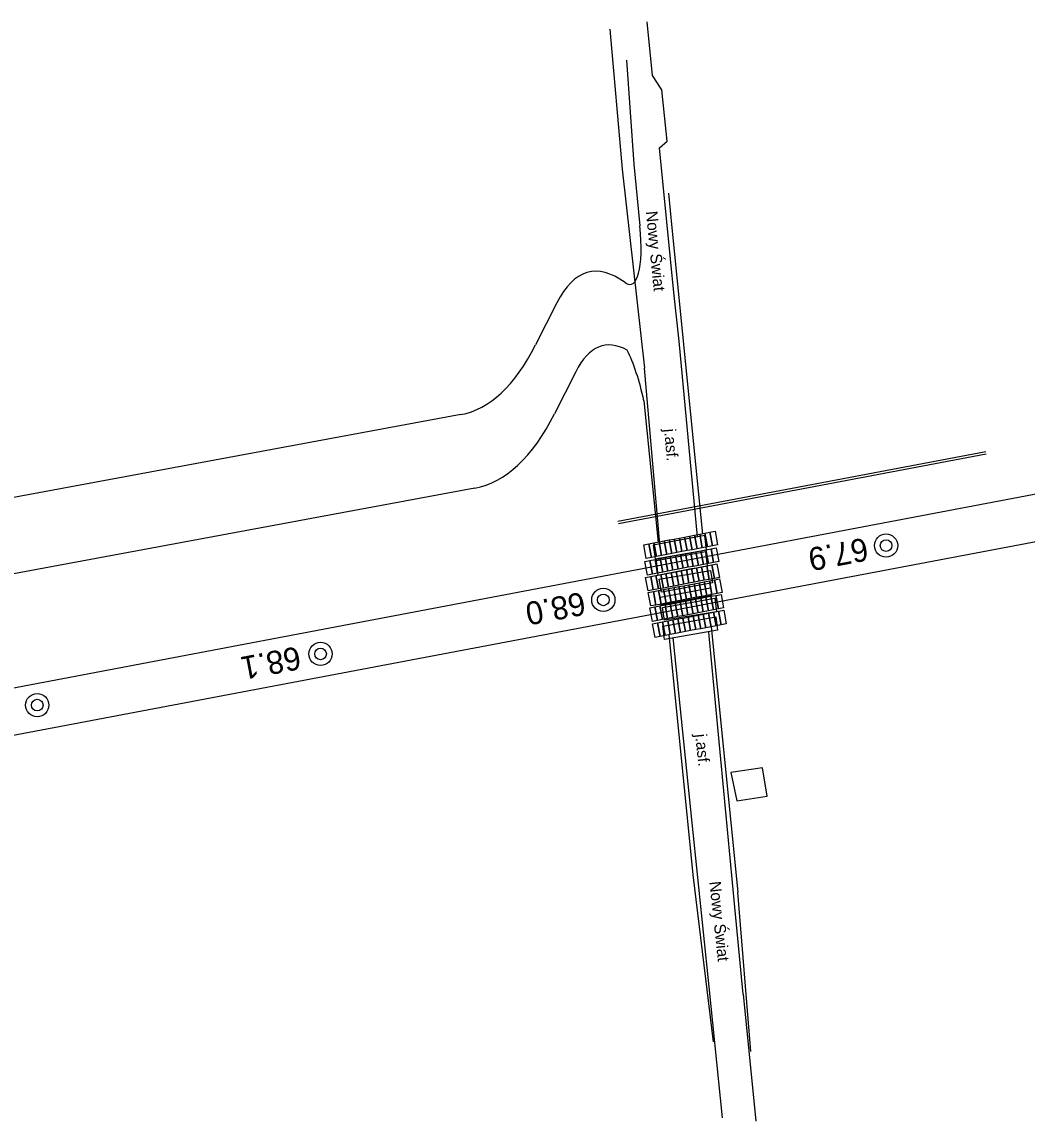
# Model space of a CAD drawing. Extents: x 6541740 to 6556805, y 5525233 to 5530361.
# Drawn here: x 6555554.3 to 6555641.5, y 5525816.3 to 5525911.7 of the extents above; entities that cross this region are included whole.
import ezdxf

# ---------------------------------------------------------------- set-up
doc = ezdxf.new("R2010")
doc.units = 0
for name, color, linetype in [('Default', 7, 'Continuous'), ('TOR_SCH-budynki', 7, 'Continuous'), ('TOR_SCH-hektometry', 7, 'Continuous'), ('TOR_SCH-obiekty projektowane', 7, 'Continuous'), ('TOR_SCH-przejazdy+drogi istniejace', 7, 'Continuous'), ('TOR_SCH-przejazdy+drogi projektowane', 7, 'Continuous'), ('TOR_SCH-tory projektowane', 7, 'Continuous')]:
    doc.layers.add(name, color=color, linetype=linetype)

# ---------------------------------------------------------------- blocks, each defined once
blk = doc.blocks.new('4010_1')
at = {"layer": 'Default'}
for radius in [0.75, 0.375]:
    blk.add_circle((0, 0), radius, dxfattribs=at)

msp = doc.modelspace()

# ---------------------------------------------------------------- linework, layer by layer
at = {"layer": 'TOR_SCH-budynki'}
msp.add_lwpolyline([(6555615.817, 5525846.569), (6555616.342, 5525844.102), (6555618.975, 5525844.513), (6555618.567, 5525846.974)], close=True, dxfattribs=at)
at = {"layer": 'TOR_SCH-obiekty projektowane'}
for p, q in [((6555606.028, 5525868.38), (6555637.959, 5525874.433)), ((6555606.065, 5525868.184), (6555637.996, 5525874.236))]:
    msp.add_line(p, q, dxfattribs=at)
at = {"layer": 'TOR_SCH-przejazdy+drogi istniejace'}
for p, q in [((6555605.315, 5525911.115), (6555606.385, 5525898.961)), ((6555609.037, 5525907.083), (6555608.566, 5525911.733)), ((6555609.841, 5525905.845), (6555609.037, 5525907.083)), ((6555610.294, 5525901.39), (6555609.841, 5525905.845)), ((6555609.623, 5525900.808), (6555610.294, 5525901.39)), ((6555610.891, 5525888.25), (6555609.623, 5525900.808)), ((6555606.385, 5525898.961), (6555608.345, 5525881.685)), ((6555613.957, 5525827.945), (6555612.481, 5525842.206)), ((6555616.889, 5525827.316), (6555616.163, 5525834.861)), ((6555615.12, 5525816.595), (6555613.957, 5525827.945)), ((6555616.889, 5525827.316), (6555617.99, 5525816.304))]:
    msp.add_line(p, q, dxfattribs=at)
for points in [[(6555612.928, 5525867.023), (6555611.343, 5525884.03), (6555610.891, 5525888.25)], [(6555609.661, 5525866.388), (6555608.345, 5525881.685)], [(6555609.884, 5525860.882), (6555614.444, 5525861.703), (6555614.575, 5525860.514), (6555610.057, 5525859.78), (6555609.884, 5525860.882)], [(6555616.163, 5525834.861), (6555613.94, 5525858.442), (6555613.911, 5525858.79)], [(6555612.481, 5525842.206), (6555610.848, 5525857.994), (6555610.82, 5525858.261)]]:
    msp.add_lwpolyline(points, dxfattribs=at)
for points in [[(6555613.575, 5525867.15), (6555609.097, 5525866.315), (6555609.268, 5525865.114), (6555613.729, 5525865.905)], [(6555613.657, 5525865.735), (6555609.349, 5525864.936), (6555609.494, 5525863.713), (6555613.807, 5525864.522)], [(6555609.601, 5525863.34), (6555614.078, 5525864.114), (6555614.227, 5525863.021), (6555609.795, 5525862.225)], [(6555609.709, 5525861.778), (6555614.053, 5525862.598), (6555614.152, 5525861.931), (6555609.793, 5525861.1)], [(6555609.918, 5525859.269), (6555614.523, 5525860.09), (6555614.683, 5525858.939), (6555610.061, 5525858.114)]]:
    msp.add_lwpolyline(points, close=True, dxfattribs=at)
at = {"layer": 'TOR_SCH-przejazdy+drogi projektowane'}
for p, q in [((6555606.773, 5525908.404), (6555607.395, 5525899.379)), ((6555607.395, 5525899.379), (6555607.929, 5525894.023)), ((6555610.407, 5525896.871), (6555610.719, 5525893.873)), ((6555610.719, 5525893.873), (6555613.372, 5525867.273)), ((6555600.722, 5525887.34), (6555598.873, 5525883.688)), ((6555602.367, 5525881.359), (6555600.517, 5525877.707)), ((6555608.288, 5525878.84), (6555609.514, 5525866.547)), ((6555592.391, 5525877.644), (6555510.496, 5525862.451)), ((6555593.6, 5525871.257), (6555511.705, 5525856.065)), ((6555610.446, 5525858.537), (6555612.527, 5525837.666)), ((6555614.129, 5525859.215), (6555616.426, 5525836.183)), ((6555612.527, 5525837.666), (6555614.286, 5525823.189)), ((6555617.577, 5525822.345), (6555616.426, 5525836.183))]:
    msp.add_line(p, q, dxfattribs=at)
for points in [[(6555611.802, 5525867.007), (6555612.028, 5525865.829), (6555611.585, 5525865.745), (6555611.36, 5525866.923)], [(6555612.245, 5525867.091), (6555612.47, 5525865.912), (6555612.028, 5525865.829), (6555611.802, 5525867.007)], [(6555612.687, 5525867.175), (6555612.912, 5525865.996), (6555612.47, 5525865.912), (6555612.245, 5525867.091)], [(6555613.129, 5525867.258), (6555613.354, 5525866.08), (6555612.912, 5525865.996), (6555612.687, 5525867.175)], [(6555613.571, 5525867.342), (6555613.796, 5525866.163), (6555613.354, 5525866.08), (6555613.129, 5525867.258)], [(6555614.013, 5525867.426), (6555614.238, 5525866.247), (6555613.796, 5525866.163), (6555613.571, 5525867.342)], [(6555614.455, 5525867.51), (6555614.68, 5525866.331), (6555614.238, 5525866.247), (6555614.013, 5525867.426)], [(6555608.707, 5525866.421), (6555608.933, 5525865.242), (6555608.49, 5525865.159), (6555608.265, 5525866.337)], [(6555609.15, 5525866.505), (6555609.375, 5525865.326), (6555608.933, 5525865.242), (6555608.707, 5525866.421)], [(6555609.592, 5525866.589), (6555609.817, 5525865.41), (6555609.375, 5525865.326), (6555609.15, 5525866.505)], [(6555610.034, 5525866.672), (6555610.259, 5525865.494), (6555609.817, 5525865.41), (6555609.592, 5525866.589)], [(6555610.476, 5525866.756), (6555610.701, 5525865.577), (6555610.259, 5525865.494), (6555610.034, 5525866.672)], [(6555610.918, 5525866.84), (6555611.143, 5525865.661), (6555610.701, 5525865.577), (6555610.476, 5525866.756)], [(6555611.36, 5525866.923), (6555611.585, 5525865.745), (6555611.143, 5525865.661), (6555610.918, 5525866.84)], [(6555614.554, 5525866.064), (6555614.779, 5525864.885), (6555614.337, 5525864.801), (6555614.112, 5525865.98)], [(6555609.691, 5525865.142), (6555609.916, 5525863.964), (6555609.474, 5525863.88), (6555609.249, 5525865.059)], [(6555610.133, 5525865.226), (6555610.358, 5525864.048), (6555609.916, 5525863.964), (6555609.691, 5525865.142)], [(6555610.575, 5525865.31), (6555610.8, 5525864.131), (6555610.358, 5525864.048), (6555610.133, 5525865.226)], [(6555611.017, 5525865.394), (6555611.242, 5525864.215), (6555610.8, 5525864.131), (6555610.575, 5525865.31)], [(6555611.459, 5525865.477), (6555611.684, 5525864.299), (6555611.242, 5525864.215), (6555611.017, 5525865.394)], [(6555611.901, 5525865.561), (6555612.127, 5525864.382), (6555611.684, 5525864.299), (6555611.459, 5525865.477)], [(6555612.344, 5525865.645), (6555612.569, 5525864.466), (6555612.127, 5525864.382), (6555611.901, 5525865.561)], [(6555612.786, 5525865.729), (6555613.011, 5525864.55), (6555612.569, 5525864.466), (6555612.344, 5525865.645)], [(6555613.228, 5525865.812), (6555613.453, 5525864.634), (6555613.011, 5525864.55), (6555612.786, 5525865.729)], [(6555613.67, 5525865.896), (6555613.895, 5525864.717), (6555613.453, 5525864.634), (6555613.228, 5525865.812)], [(6555614.112, 5525865.98), (6555614.337, 5525864.801), (6555613.895, 5525864.717), (6555613.67, 5525865.896)], [(6555608.807, 5525864.975), (6555609.032, 5525863.796), (6555608.589, 5525863.713), (6555608.364, 5525864.891)], [(6555609.249, 5525865.059), (6555609.474, 5525863.88), (6555609.032, 5525863.796), (6555608.807, 5525864.975)], [(6555611.967, 5525864.182), (6555612.192, 5525863.003), (6555611.75, 5525862.92), (6555611.525, 5525864.098)], [(6555612.409, 5525864.266), (6555612.635, 5525863.087), (6555612.192, 5525863.003), (6555611.967, 5525864.182)], [(6555612.852, 5525864.349), (6555613.077, 5525863.171), (6555612.635, 5525863.087), (6555612.409, 5525864.266)], [(6555613.294, 5525864.433), (6555613.519, 5525863.254), (6555613.077, 5525863.171), (6555612.852, 5525864.349)], [(6555613.736, 5525864.517), (6555613.961, 5525863.338), (6555613.519, 5525863.254), (6555613.294, 5525864.433)], [(6555614.178, 5525864.601), (6555614.403, 5525863.422), (6555613.961, 5525863.338), (6555613.736, 5525864.517)], [(6555614.62, 5525864.684), (6555614.845, 5525863.506), (6555614.403, 5525863.422), (6555614.178, 5525864.601)], [(6555608.872, 5525863.596), (6555609.097, 5525862.417), (6555608.655, 5525862.333), (6555608.43, 5525863.512)], [(6555609.314, 5525863.68), (6555609.54, 5525862.501), (6555609.097, 5525862.417), (6555608.872, 5525863.596)], [(6555609.757, 5525863.763), (6555609.982, 5525862.585), (6555609.54, 5525862.501), (6555609.314, 5525863.68)], [(6555610.199, 5525863.847), (6555610.424, 5525862.668), (6555609.982, 5525862.585), (6555609.757, 5525863.763)], [(6555610.641, 5525863.931), (6555610.866, 5525862.752), (6555610.424, 5525862.668), (6555610.199, 5525863.847)], [(6555611.083, 5525864.014), (6555611.308, 5525862.836), (6555610.866, 5525862.752), (6555610.641, 5525863.931)], [(6555611.525, 5525864.098), (6555611.75, 5525862.92), (6555611.308, 5525862.836), (6555611.083, 5525864.014)], [(6555613.964, 5525863.207), (6555614.189, 5525862.028), (6555613.747, 5525861.944), (6555613.522, 5525863.123)], [(6555614.406, 5525863.291), (6555614.631, 5525862.112), (6555614.189, 5525862.028), (6555613.964, 5525863.207)], [(6555614.848, 5525863.374), (6555615.073, 5525862.196), (6555614.631, 5525862.112), (6555614.406, 5525863.291)], [(6555609.1, 5525862.286), (6555609.325, 5525861.107), (6555608.883, 5525861.023), (6555608.658, 5525862.202)], [(6555609.542, 5525862.369), (6555609.767, 5525861.191), (6555609.325, 5525861.107), (6555609.1, 5525862.286)], [(6555609.984, 5525862.453), (6555610.21, 5525861.274), (6555609.767, 5525861.191), (6555609.542, 5525862.369)], [(6555610.427, 5525862.537), (6555610.652, 5525861.358), (6555610.21, 5525861.274), (6555609.984, 5525862.453)], [(6555610.869, 5525862.621), (6555611.094, 5525861.442), (6555610.652, 5525861.358), (6555610.427, 5525862.537)], [(6555611.311, 5525862.704), (6555611.536, 5525861.526), (6555611.094, 5525861.442), (6555610.869, 5525862.621)], [(6555611.753, 5525862.788), (6555611.978, 5525861.609), (6555611.536, 5525861.526), (6555611.311, 5525862.704)], [(6555612.195, 5525862.872), (6555612.42, 5525861.693), (6555611.978, 5525861.609), (6555611.753, 5525862.788)], [(6555612.637, 5525862.956), (6555612.862, 5525861.777), (6555612.42, 5525861.693), (6555612.195, 5525862.872)], [(6555613.079, 5525863.039), (6555613.305, 5525861.861), (6555612.862, 5525861.777), (6555612.637, 5525862.956)], [(6555613.522, 5525863.123), (6555613.747, 5525861.944), (6555613.305, 5525861.861), (6555613.079, 5525863.039)], [(6555610.999, 5525861.278), (6555611.224, 5525860.099), (6555610.782, 5525860.015), (6555610.557, 5525861.194)], [(6555611.441, 5525861.361), (6555611.666, 5525860.183), (6555611.224, 5525860.099), (6555610.999, 5525861.278)], [(6555611.884, 5525861.445), (6555612.109, 5525860.266), (6555611.666, 5525860.183), (6555611.441, 5525861.361)], [(6555612.326, 5525861.529), (6555612.551, 5525860.35), (6555612.109, 5525860.266), (6555611.884, 5525861.445)], [(6555612.768, 5525861.613), (6555612.993, 5525860.434), (6555612.551, 5525860.35), (6555612.326, 5525861.529)], [(6555613.21, 5525861.696), (6555613.435, 5525860.518), (6555612.993, 5525860.434), (6555612.768, 5525861.613)], [(6555613.652, 5525861.78), (6555613.877, 5525860.601), (6555613.435, 5525860.518), (6555613.21, 5525861.696)], [(6555614.094, 5525861.864), (6555614.319, 5525860.685), (6555613.877, 5525860.601), (6555613.652, 5525861.78)], [(6555614.536, 5525861.948), (6555614.761, 5525860.769), (6555614.319, 5525860.685), (6555614.094, 5525861.864)], [(6555614.978, 5525862.031), (6555615.204, 5525860.853), (6555614.761, 5525860.769), (6555614.536, 5525861.948)], [(6555609.231, 5525860.943), (6555609.456, 5525859.764), (6555609.014, 5525859.68), (6555608.789, 5525860.859)], [(6555609.673, 5525861.026), (6555609.898, 5525859.848), (6555609.456, 5525859.764), (6555609.231, 5525860.943)], [(6555610.115, 5525861.11), (6555610.34, 5525859.931), (6555609.898, 5525859.848), (6555609.673, 5525861.026)], [(6555610.557, 5525861.194), (6555610.782, 5525860.015), (6555610.34, 5525859.931), (6555610.115, 5525861.11)], [(6555613.441, 5525860.316), (6555613.666, 5525859.137), (6555613.224, 5525859.053), (6555612.999, 5525860.232)], [(6555613.883, 5525860.399), (6555614.108, 5525859.221), (6555613.666, 5525859.137), (6555613.441, 5525860.316)], [(6555614.325, 5525860.483), (6555614.55, 5525859.304), (6555614.108, 5525859.221), (6555613.883, 5525860.399)], [(6555614.767, 5525860.567), (6555614.992, 5525859.388), (6555614.55, 5525859.304), (6555614.325, 5525860.483)], [(6555615.21, 5525860.651), (6555615.435, 5525859.472), (6555614.992, 5525859.388), (6555614.767, 5525860.567)], [(6555609.462, 5525859.562), (6555609.687, 5525858.383), (6555609.245, 5525858.3), (6555609.02, 5525859.478)], [(6555609.904, 5525859.646), (6555610.129, 5525858.467), (6555609.687, 5525858.383), (6555609.462, 5525859.562)], [(6555610.346, 5525859.73), (6555610.571, 5525858.551), (6555610.129, 5525858.467), (6555609.904, 5525859.646)], [(6555610.788, 5525859.813), (6555611.013, 5525858.635), (6555610.571, 5525858.551), (6555610.346, 5525859.73)], [(6555611.23, 5525859.897), (6555611.455, 5525858.718), (6555611.013, 5525858.635), (6555610.788, 5525859.813)], [(6555611.672, 5525859.981), (6555611.897, 5525858.802), (6555611.455, 5525858.718), (6555611.23, 5525859.897)], [(6555612.115, 5525860.064), (6555612.34, 5525858.886), (6555611.897, 5525858.802), (6555611.672, 5525859.981)], [(6555612.557, 5525860.148), (6555612.782, 5525858.969), (6555612.34, 5525858.886), (6555612.115, 5525860.064)], [(6555612.999, 5525860.232), (6555613.224, 5525859.053), (6555612.782, 5525858.969), (6555612.557, 5525860.148)]]:
    msp.add_lwpolyline(points, close=True, dxfattribs=at)
for centre, major_axis, start_param, end_param in [((6555605.801, 5525896.073), (-1.35, 7.123), 2.87906, 4.373417), ((6555611.664, 5525847.546), (-8.055, 42.493), 6.020653, 6.597201), ((6555611.664, 5525847.546), (-6.844, 36.107), 6.075316, 6.597201), ((6555574.395, 5525972.706), (-18.018, 95.057), 3.140618, 3.455608), ((6555606.69, 5525877.613), (-1.35, 7.123), 4.837905, 5.571797), ((6555574.395, 5525972.706), (-19.229, 101.444), 3.140618, 3.455608)]:
    msp.add_ellipse(centre, major_axis=major_axis, ratio=0.25, start_param=start_param, end_param=end_param, dxfattribs=at)
at = {"layer": 'TOR_SCH-tory projektowane'}
for p, q in [((6555661.881, 5525874.434), (6555417.835, 5525828.174)), ((6555662.569, 5525870.442), (6555511.666, 5525841.838))]:
    msp.add_line(p, q, dxfattribs=at)

# ---------------------------------------------------------------- block references
at = {"layer": 'TOR_SCH-hektometry', "xscale": 1.345963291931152, "yscale": 1.345963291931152}
for p in [(6555629.311, 5525866.269), (6555604.759, 5525861.555), (6555580.203, 5525856.861), (6555555.605, 5525852.415)]:
    msp.add_blockref('4010_1', p, dxfattribs=at)

# ---------------------------------------------------------------- texts
at = {"layer": 'TOR_SCH-hektometry'}
for s, p in [('67.9', (6555627.535, 5525866.976)), ('68.0', (6555602.983, 5525862.262)), ('68.1', (6555578.268, 5525857.538))]:
    msp.add_text(s, height=2, rotation=190.76907, dxfattribs=at).set_placement(p)
at = {"layer": 'TOR_SCH-przejazdy+drogi istniejace'}
for s, rotation, p in [('Nowy Świat', 275.66644, (6555608.453, 5525895.271)), ('j.asf.', 275.02348, (6555610.031, 5525876.377)), ('j.asf.', 275.97049, (6555612.729, 5525849.867)), ('Nowy Świat', 276.17146, (6555613.96, 5525837.07))]:
    msp.add_text(s, height=1, rotation=rotation, dxfattribs=at).set_placement(p)

doc.saveas('drawing.dxf')
